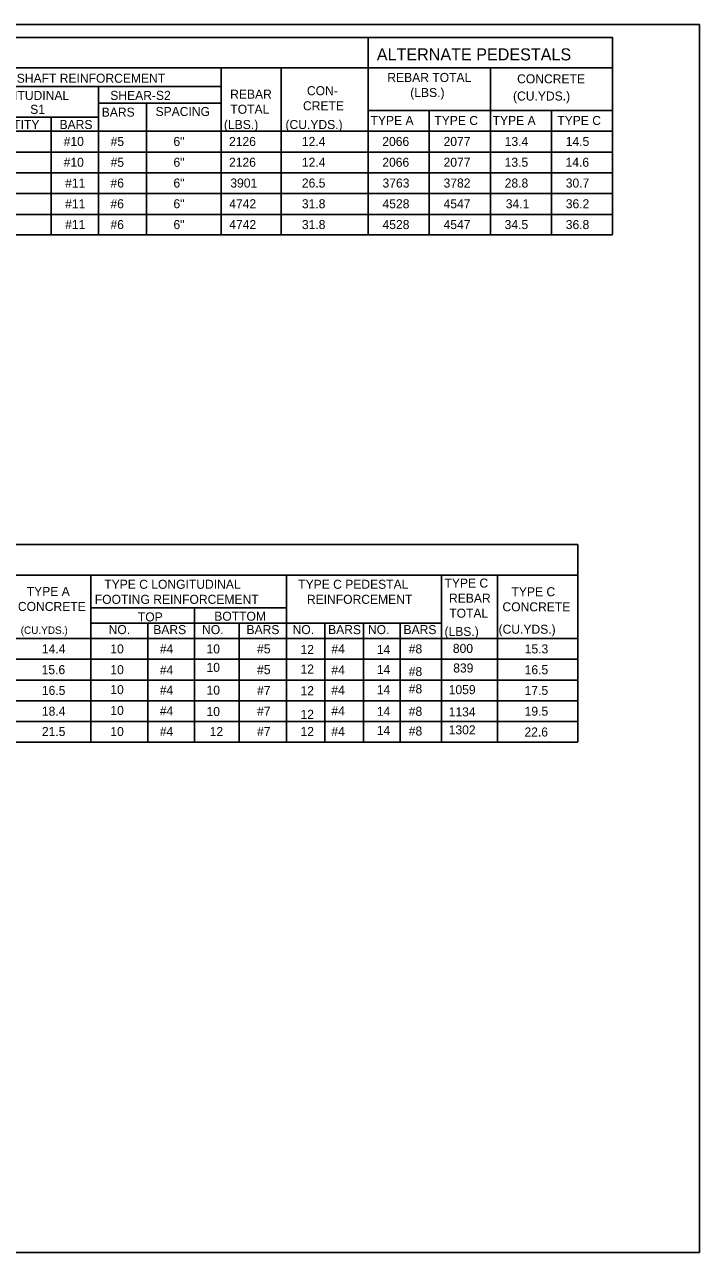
# Model space of a CAD drawing. Extents: x -439.1 to -407.9, y -458.1 to -437.7.
# Drawn here: x -419.06 to -407.86, y -458.06 to -437.69 of the extents above; entities that cross this region are included whole.
import ezdxf

# ---------------------------------------------------------------- set-up
doc = ezdxf.new("R2010")
doc.units = 0
for name, color, linetype in [('Draft_Named_Boundary', 7, 'Continuous'), ('Level 4', 7, 'Continuous'), ('Level 45', 7, 'Continuous')]:
    doc.layers.add(name, color=color, linetype=linetype)

msp = doc.modelspace()

# ---------------------------------------------------------------- linework, layer by layer
at = {"layer": 'Draft_Named_Boundary'}
msp.add_lwpolyline([(-439.109, -458.061), (-407.859, -458.061), (-407.859, -437.686), (-439.109, -437.686)], close=True, dxfattribs=at)
at = {"layer": 'Level 4'}
for p, q in [((-438.787, -437.899), (-409.301, -437.899)), ((-413.355, -437.899), (-413.355, -441.17)), ((-409.301, -437.894), (-409.301, -441.17)), ((-438.787, -438.405), (-409.301, -438.405)), ((-415.795, -438.405), (-415.795, -441.176)), ((-414.8, -438.405), (-414.8, -441.17)), ((-411.328, -438.405), (-411.328, -441.17)), ((-426.109, -438.712), (-415.795, -438.712)), ((-417.83, -438.712), (-417.83, -441.17)), ((-417.83, -438.988), (-415.795, -438.988)), ((-417.031, -438.988), (-417.031, -441.161)), ((-419.872, -439.223), (-417.83, -439.223)), ((-418.615, -439.223), (-418.615, -441.178)), ((-413.355, -439.11), (-409.301, -439.11)), ((-412.342, -439.11), (-412.342, -441.17)), ((-410.315, -439.11), (-410.315, -441.17)), ((-438.787, -439.458), (-409.301, -439.458)), ((-438.787, -439.803), (-409.301, -439.803)), ((-438.787, -440.148), (-409.301, -440.148)), ((-438.787, -440.492), (-409.301, -440.492)), ((-438.787, -440.837), (-409.301, -440.837)), ((-438.787, -441.177), (-409.301, -441.177)), ((-438.787, -446.314), (-409.879, -446.314)), ((-409.879, -446.314), (-409.879, -449.589)), ((-438.787, -446.821), (-409.879, -446.821)), ((-417.956, -446.821), (-417.956, -449.589)), ((-414.712, -446.821), (-414.712, -449.589)), ((-412.136, -446.821), (-412.136, -449.589)), ((-412.136, -446.821), (-412.136, -449.589)), ((-411.209, -446.821), (-411.209, -449.589)), ((-417.956, -447.364), (-414.712, -447.364)), ((-416.237, -447.364), (-416.237, -449.589)), ((-417.956, -447.619), (-412.136, -447.619)), ((-417.013, -447.619), (-417.013, -449.589)), ((-415.496, -447.619), (-415.496, -449.589)), ((-414.072, -447.619), (-414.072, -449.589)), ((-413.433, -447.619), (-413.433, -449.589)), ((-412.822, -447.619), (-412.822, -449.589)), ((-438.787, -447.874), (-409.879, -447.874)), ((-438.787, -448.218), (-409.879, -448.218)), ((-438.787, -448.563), (-409.879, -448.563)), ((-438.787, -448.908), (-409.879, -448.908)), ((-438.787, -449.252), (-409.879, -449.252)), ((-438.787, -449.593), (-409.879, -449.593))]:
    msp.add_line(p, q, dxfattribs=at)

# ---------------------------------------------------------------- texts
for s, height, p in [('ALTERNATE PEDESTALS', 0.2, (-413.212, -438.281)), ('SHAFT REINFORCEMENT', 0.15, (-419.186, -438.652)), ('REBAR TOTAL', 0.15, (-413.038, -438.639)), ('CONCRETE', 0.15, (-410.884, -438.662)), ('LONGITUDINAL', 0.15, (-419.798, -438.937)), ('SHEAR-S2', 0.15, (-417.634, -438.937)), ('REBAR', 0.15, (-415.645, -438.917)), ('CON-', 0.15, (-414.371, -438.859)), ('(LBS.)', 0.15, (-412.657, -438.889)), ('(CU.YDS.)', 0.15, (-410.952, -438.947)), ('S1', 0.15, (-418.963, -439.168)), ('BARS', 0.15, (-417.776, -439.215)), ('SPACING', 0.15, (-416.883, -439.204)), ('TOTAL', 0.15, (-415.642, -439.167)), ('CRETE', 0.15, (-414.437, -439.109)), ('QUANTITY', 0.15, (-419.824, -439.42)), ('BARS', 0.15, (-418.476, -439.42)), ('(CU.YDS.)', 0.15, (-414.727, -439.42)), ('TYPE A', 0.15, (-413.316, -439.353)), ('TYPE C', 0.15, (-412.257, -439.353)), ('TYPE A', 0.15, (-411.29, -439.353)), ('TYPE C', 0.15, (-410.217, -439.353)), ('2066', 0.15, (-413.121, -439.701)), ('2077', 0.15, (-412.104, -439.701)), ('13.4', 0.15, (-411.09, -439.701)), ('14.5', 0.15, (-410.077, -439.701)), ('2066', 0.15, (-413.121, -440.046)), ('2077', 0.15, (-412.104, -440.046)), ('13.5', 0.15, (-411.091, -440.046)), ('14.6', 0.15, (-410.08, -440.046)), ('3763', 0.15, (-413.117, -440.391)), ('3782', 0.15, (-412.104, -440.391)), ('28.8', 0.15, (-411.09, -440.391)), ('30.7', 0.15, (-410.077, -440.391)), ('4528', 0.15, (-413.117, -440.735)), ('4547', 0.15, (-412.104, -440.735)), ('34.1', 0.15, (-411.072, -440.735)), ('36.2', 0.15, (-410.077, -440.735)), ('4528', 0.15, (-413.117, -441.08)), ('4547', 0.15, (-412.104, -441.08)), ('34.5', 0.15, (-411.091, -441.08)), ('36.8', 0.15, (-410.077, -441.08)), ('TYPE A', 0.15, (-419.02, -447.167)), ('TYPE C LONGITUDINAL', 0.15, (-417.734, -447.049)), ('TYPE C PEDESTAL', 0.15, (-414.516, -447.049)), ('TYPE C', 0.15, (-412.089, -447.029)), ('TYPE C', 0.15, (-410.977, -447.173)), ('FOOTING REINFORCEMENT', 0.15, (-417.891, -447.299)), ('REINFORCEMENT', 0.15, (-414.372, -447.299)), ('REBAR', 0.15, (-412.014, -447.279)), ('CONCRETE', 0.15, (-419.167, -447.417)), ('BOTTOM', 0.15, (-415.909, -447.579)), ('TOTAL', 0.15, (-412.01, -447.529)), ('CONCRETE', 0.15, (-411.127, -447.423)), ('TOP', 0.15, (-417.176, -447.591)), ('(CU.YDS.)', 0.15, (-411.192, -447.795)), ('(CU.YDS.)', 0.1237, (-419.121, -447.798)), ('NO.', 0.15, (-417.662, -447.801)), ('BARS', 0.15, (-416.921, -447.801)), ('NO.', 0.15, (-416.111, -447.801)), ('BARS', 0.15, (-415.374, -447.801)), ('NO.', 0.15, (-414.609, -447.801)), ('BARS', 0.15, (-414.02, -447.801)), ('NO.', 0.15, (-413.359, -447.801)), ('BARS', 0.15, (-412.769, -447.801)), ('(LBS.)', 0.15, (-412.089, -447.832)), ('15.3', 0.15, (-410.758, -448.121)), ('16.5', 0.15, (-410.759, -448.466)), ('17.5', 0.15, (-410.759, -448.81)), ('19.5', 0.15, (-410.759, -449.155)), ('22.6', 0.15, (-410.762, -449.5))]:
    msp.add_text(s, height=height, dxfattribs=at).set_placement(p)
at = {"layer": 'Level 45'}
for s, p in [('(LBS.)', (-415.748, -439.42)), ('#10', (-418.407, -439.701)), ('#5', (-417.628, -439.701)), ('6"', (-416.586, -439.701)), ('2126', (-415.664, -439.701)), ('12.4', (-414.455, -439.701)), ('#10', (-418.407, -440.046)), ('#5', (-417.628, -440.046)), ('6"', (-416.586, -440.046)), ('2126', (-415.664, -440.046)), ('12.4', (-414.455, -440.046)), ('#11', (-418.383, -440.391)), ('#6', (-417.631, -440.391)), ('6"', (-416.586, -440.391)), ('3901', (-415.642, -440.391)), ('26.5', (-414.455, -440.391)), ('#11', (-418.383, -440.735)), ('#6', (-417.631, -440.735)), ('6"', (-416.586, -440.735)), ('4742', (-415.66, -440.735)), ('31.8', (-414.455, -440.735)), ('#11', (-418.383, -441.08)), ('#6', (-417.631, -441.08)), ('6"', (-416.586, -441.08)), ('4742', (-415.66, -441.08)), ('31.8', (-414.455, -441.08)), ('14.4', (-418.769, -448.121)), ('10', (-417.633, -448.121)), ('#4', (-416.812, -448.121)), ('10', (-416.037, -448.121)), ('#5', (-415.198, -448.121)), ('12', (-414.478, -448.131)), ('#4', (-413.965, -448.121)), ('14', (-413.212, -448.131)), ('#8', (-412.682, -448.121)), ('800', (-411.95, -448.113)), ('15.6', (-418.773, -448.466)), ('10', (-417.633, -448.466)), ('#4', (-416.812, -448.471)), ('10', (-416.037, -448.428)), ('#5', (-415.198, -448.466)), ('12', (-414.478, -448.456)), ('#4', (-413.965, -448.471)), ('14', (-413.212, -448.464)), ('#8', (-412.682, -448.497)), ('839', (-411.944, -448.438)), ('10', (-417.633, -448.797)), ('#4', (-416.812, -448.804)), ('10', (-416.037, -448.806)), ('#4', (-413.965, -448.804)), ('14', (-413.212, -448.798)), ('#8', (-412.682, -448.784)), ('1059', (-412.019, -448.798)), ('16.5', (-418.769, -448.81)), ('#7', (-415.198, -448.81)), ('12', (-414.478, -448.815)), ('18.4', (-418.769, -449.155)), ('10', (-417.633, -449.142)), ('#4', (-416.812, -449.151)), ('10', (-416.037, -449.161)), ('#7', (-415.198, -449.155)), ('12', (-414.478, -449.208)), ('#4', (-413.965, -449.151)), ('14', (-413.212, -449.157)), ('#8', (-412.682, -449.157)), ('1134', (-412.019, -449.166)), ('21.5', (-418.769, -449.492)), ('10', (-417.633, -449.492)), ('#4', (-416.812, -449.491)), ('12', (-415.985, -449.492)), ('#7', (-415.198, -449.492)), ('12', (-414.478, -449.492)), ('#4', (-413.965, -449.491)), ('14', (-413.212, -449.474)), ('#8', (-412.682, -449.484)), ('1302', (-412.019, -449.465))]:
    msp.add_text(s, height=0.15, dxfattribs=at).set_placement(p)

doc.saveas('drawing.dxf')
